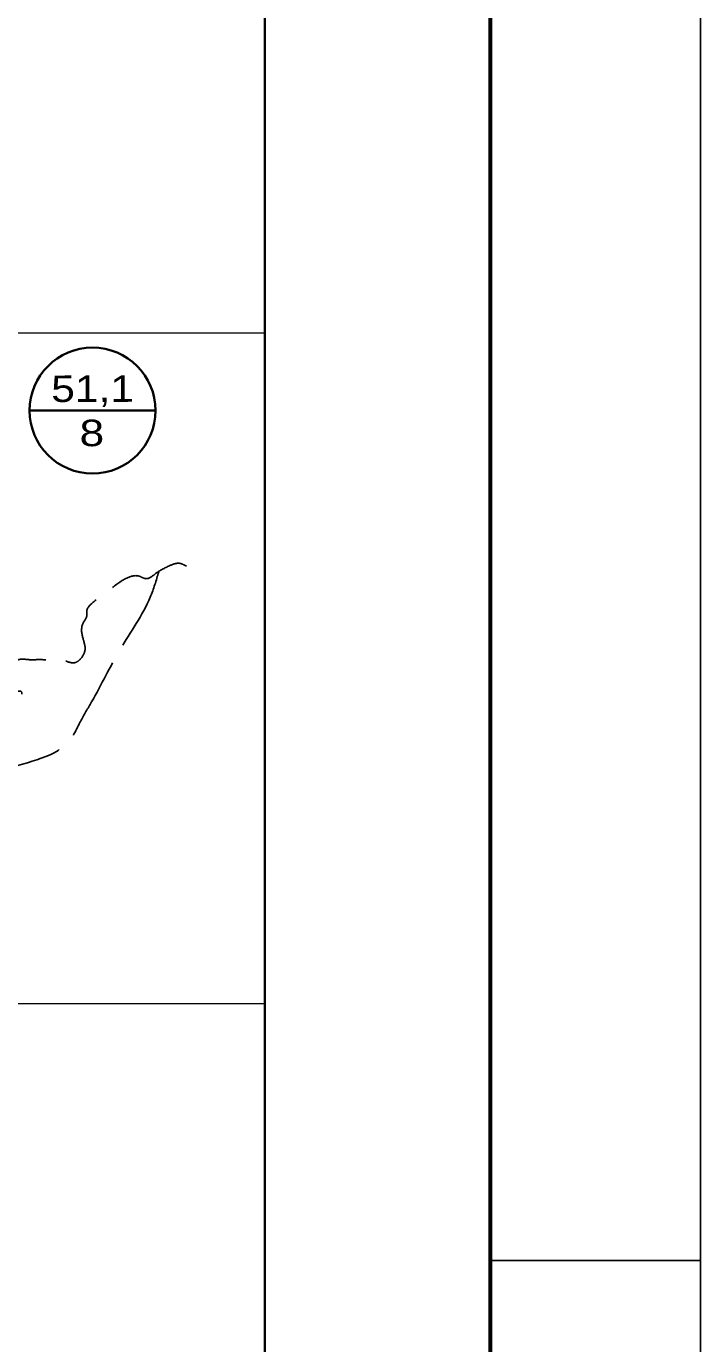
# Model space of a CAD drawing. Extents: x 0 to 1682, y 0 to 1188.
# Drawn here: x 1617.7 to 1681.8, y 586 to 711.2 of the extents above; entities that cross this region are included whole.
import ezdxf
from ezdxf.enums import TextEntityAlignment as Align

# ---------------------------------------------------------------- set-up
doc = ezdxf.new("R2010")
doc.units = 0
doc.header["$LTSCALE"] = 1.3
doc.linetypes.add('LONG_DASHED', pattern=[7.5, 6, -1.5])
for name, color, linetype, lineweight in [('5', 7, 'LONG_DASHED', 25), ('63', 7, 'Continuous', 25), ('9', 7, 'Continuous', 40)]:
    doc.layers.add(name, color=color, linetype=linetype, lineweight=lineweight)

msp = doc.modelspace()

# ---------------------------------------------------------------- linework, layer by layer
at = {"layer": '5'}
for points in [[(1632.944, 659.876), (1632.249, 660.14), (1631.333, 659.901), (1630.019, 659.157), (1629.074, 658.68), (1628.452, 658.915), (1627.196, 658.69), (1625.529, 657.53), (1623.995, 656.356), (1623.48, 655.644), (1623.481, 655.171), (1623.099, 654.385), (1623.103, 653.053), (1623.313, 651.929), (1622.813, 650.98), (1622.43, 650.727), (1621.331, 650.914), (1620.662, 651.12), (1620.082, 650.987), (1619.206, 650.984), (1618.046, 650.981), (1616.972, 650.978), (1616.273, 650.603), (1615.792, 650.305), (1615.541, 649.998), (1615.542, 649.45), (1615.839, 649.034), (1616.049, 648.541), (1616.324, 648.049), (1616.653, 647.94), (1617.255, 647.942), (1617.256, 647.547), (1616.884, 647.436), (1616.348, 647.314), (1615.911, 647.006), (1615.638, 646.665), (1615.64, 645.975), (1615.642, 645.449), (1615.468, 644.966), (1614.933, 644.657)], [(1630.321, 659.326), (1629.513, 656.919), (1626.666, 651.968), (1623.932, 646.96), (1622.871, 645.103), (1621.978, 643.472), (1615.59, 640.532), (1609.203, 637.367), (1603.208, 634.541), (1598.277, 632.11), (1594.355, 630.357), (1591.939, 629.323)]]:
    msp.add_spline(points, degree=3, dxfattribs=at)
at = {"layer": '63'}
for p, q in [((1681.832, -0.119), (1681.832, 1187.881)), ((1681.832, -0.119), (1681.832, 1187.881)), ((1661.832, 593.881), (1681.832, 593.881))]:
    msp.add_line(p, q, dxfattribs=at)
at = {"layer": '63', "lineweight": 35}
msp.add_line((1640.404, 427.142), (1640.404, 783.93), dxfattribs=at)
at = {"layer": '63', "lineweight": 13}
for p, q in [((1640.404, 681.991), (952.314, 681.991)), ((1640.404, 618.279), (952.314, 618.279))]:
    msp.add_line(p, q, dxfattribs=at)
at = {"layer": '63'}
msp.add_lwpolyline([(-0.168, -0.119), (1681.832, -0.119), (1681.832, 1187.881)], dxfattribs=at)
at = {"layer": '63', "lineweight": 60}
msp.add_lwpolyline([(49.832, 1167.881), (1661.832, 1167.881), (1661.832, 19.881), (1311.832, 19.881)], dxfattribs=at)
at = {"layer": '9', "lineweight": 35}
msp.add_line((1618.041, 674.65), (1630.011, 674.65), dxfattribs=at)
msp.add_circle((1624.026, 674.65), 5.985, dxfattribs=at)

# ---------------------------------------------------------------- texts
at = {"layer": '9'}
for s, width, p in [('51,1', 1.2, (1624.036, 675.47)), ('8', 1.25, (1623.962, 671.267))]:
    msp.add_text(s, height=2.52, rotation=0.17, dxfattribs=dict(at, width=width)).set_placement(p, align=Align.CENTER)

doc.saveas('drawing.dxf')
